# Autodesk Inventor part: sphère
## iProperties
Created: 2002-06
Part Number: sphère
Material: Par défaut
Document SubType Name: Modélisation
Designer: REVEST Pierre
Control State: 0
Master: False
Checked Out: False
Shininess: 70.0
Length Units: 11269
Angle Units: 11279
Time Units: 11290
Mass Units: 11283
Length Display Precision: 3
Angle Display Precision: 2
Density: 0.0
Volumn: 0.0
Area: 0.0
PropertySet Name: Model Information
Author: REVEST Pierre
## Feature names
1. Révolution1 [Revolution]
2. Extrusion1
3. Extrusion2
